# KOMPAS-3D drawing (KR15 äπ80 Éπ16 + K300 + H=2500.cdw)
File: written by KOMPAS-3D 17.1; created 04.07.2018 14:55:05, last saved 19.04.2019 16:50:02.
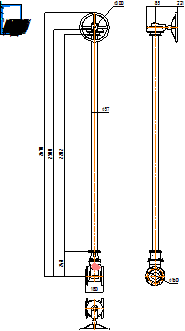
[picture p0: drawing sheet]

Sheet 1: A4, portrait

Title block, sheet 1: name: KR15 Ду80 Ру16 + / K300 + H=2500; material: Внимание! Данный продукт является объектом авторского права ООО «Торговый Дом АДЛ». / Запрещается изменение, копирование, распространение / (в том числе путем копирования на другие сайты и ресурсы в Интернете) / или любое иное использование информации и объектов без предварительного / согласия правообладателя (ООО «Торговый Дом АДЛ»).; mass: 36,7; sheets: 1; organisation: ООО "Торговый дом АДЛ"; sheet format: A4; stored path: \\adlc.lan\data\АДЛ_ПКД\3D-модели\ADL production\Клиновые задвижки серии KR ГРАНАР\Клиновые задвижки KR15 со стационарным удлинением\KOMPAS 2D\KR15 Ду80 Ру16 + K300 + H=2500.cdw

Views: Спереди 4, Проекционный вид 5, Проекционный вид 6
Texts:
  kka
  adl
Dimensions and other numbers on the sheet: 2500; 2202; 2670; 300; 57; 248; 180; 221; 85; 160; 1:1; 1; 36,7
